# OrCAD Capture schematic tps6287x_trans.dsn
size D; title: TPS6287x: 2.7-V to 6-V Input Synchronous Buck Converter; rev: 1.0; note: Datasheet: <slvsfj3b>     EVM: <slvuc13>; note: Synchronous Step Down Converter
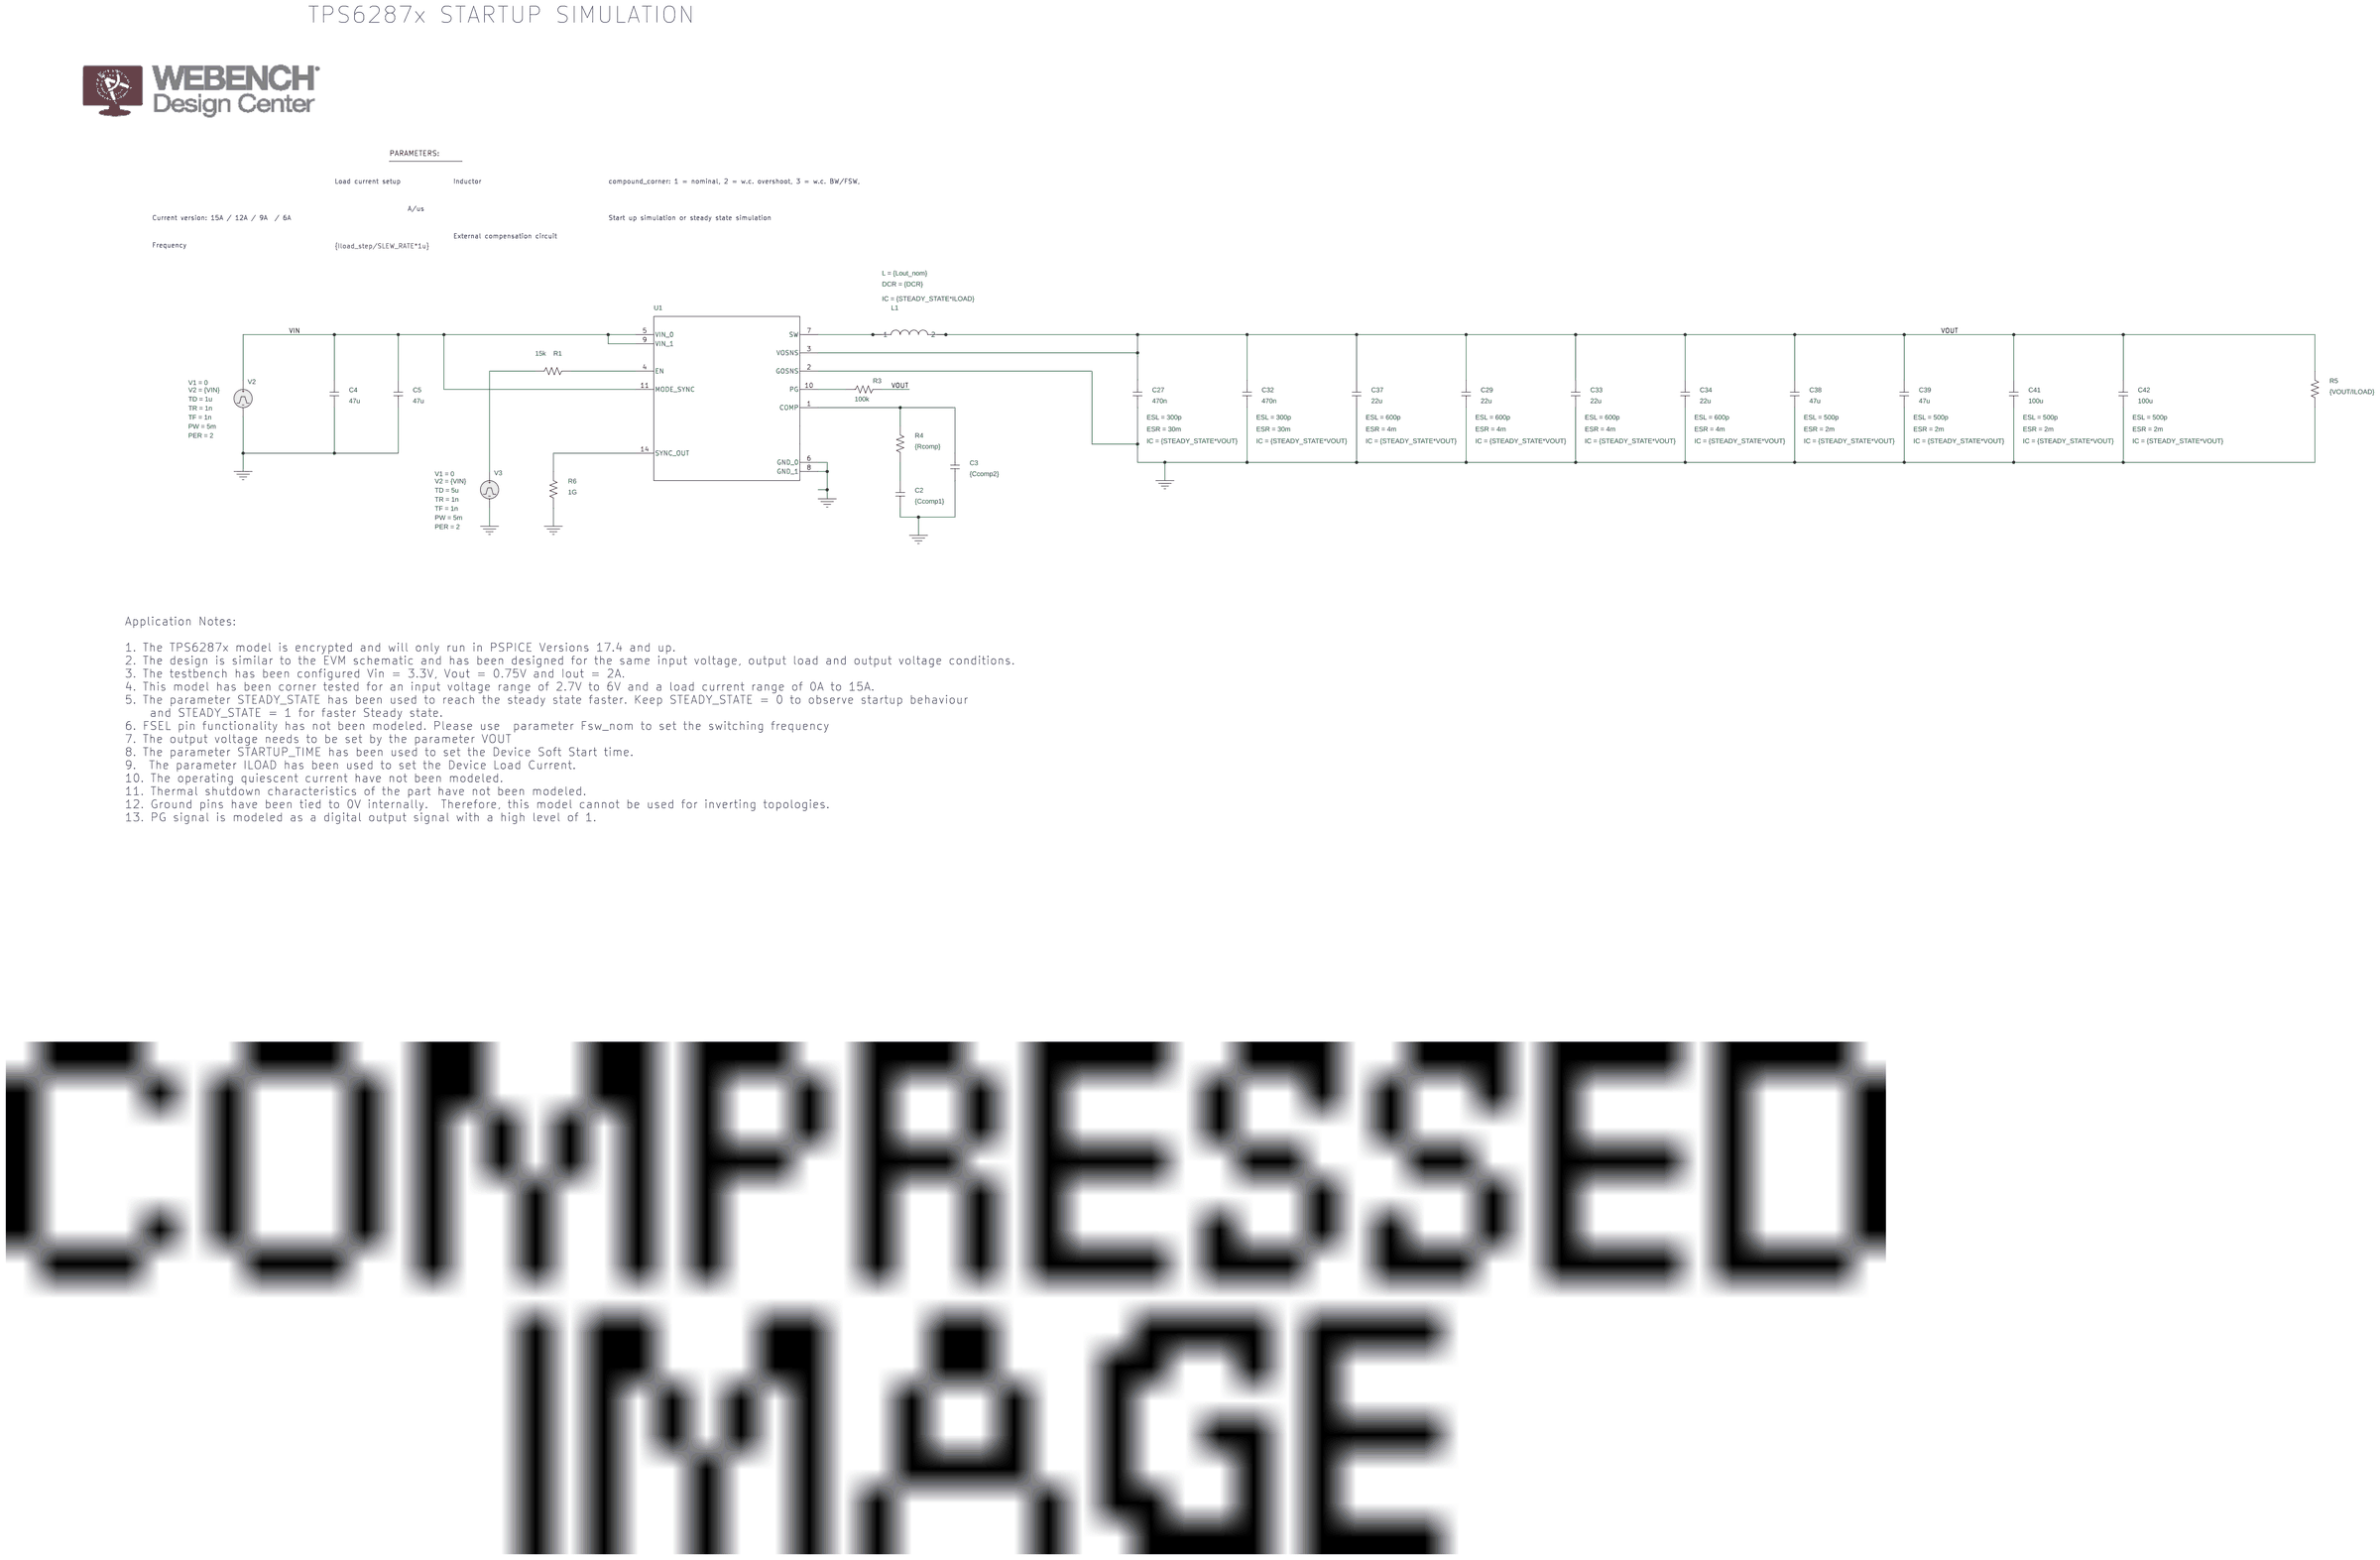
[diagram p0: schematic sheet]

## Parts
1  PARAM
C2  {Ccomp1}  [cap196]
C3  {Ccomp2}  [cap196]
C4  47u  [cap196]
C5  47u  [cap196]
C27  470n  [RAD/CK05]
C29  22u  [RAD/CK05]
C32  470n  [RAD/CK05]
C33  22u  [RAD/CK05]
C34  22u  [RAD/CK05]
C37  22u  [RAD/CK05]
C38  47u  [RAD/CK05]
C39  47u  [RAD/CK05]
C41  100u  [RAD/CK05]
C42  100u  [RAD/CK05]
L1  LDCR
R1  15k  [AXRC05]
R3  100k  [AXRC05]
R4  {Rcomp}  [AXRC05]
R5  {VOUT/ILOAD}  [AXRC05]
R6  1G  [AXRC05]
U1  Value  [RXS0016A-MFG]
V2  VPULSE
V3  VPULSE

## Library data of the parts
1 = PARAM: Ccomp1: 1.8n; Ccomp2: 10p; DCR: 1.7m; Fsw_nom: 3MEG; Fsw_tol_percent: 10; ILOAD: 2; IMAX: 15; Iload_pulse_delay: 60u; Iload_pulse_width: 30u; Iload_step: 10; Lout_nom: 110n; Lout_tol_percent: 20; Rcomp: 2.43k; SLEW_RATE: 20; STARTUP: {1-STEADY_STATE}; STARTUP_TIME: 0.3m; STEADY_STATE: 0; Trise: {Iload_step/SLEW_RATE*1u}; VIN: 3.3; VOUT: 0.75
C2-C5 = C
C27 C32 = C: AppProp: InductiveSlave:SRF;SRF:1.3403e+7;PrevCap:470n;PrevESL:300p; ESL: 300p; ESR: 30m; IC: {STEADY_STATE*VOUT}
C29 C33 C34 C37 = C: AppProp: InductiveSlave:SRF;SRF:1.3403e+7;PrevCap:470n;PrevESL:300p; ESL: 600p; ESR: 4m; IC: {STEADY_STATE*VOUT}
C38 C39 C41 C42 = C: AppProp: InductiveSlave:SRF;SRF:1.3403e+7;PrevCap:470n;PrevESL:300p; ESL: 500p; ESR: 2m; IC: {STEADY_STATE*VOUT}
L1 = LDCR: DCR: {DCR}; IC: {STEADY_STATE*ILOAD}; L: {Lout_nom}
R1 R3-R6 = R
U1 = TPS6287x_TRANS
V2 = VPULSE: PER: 2; PW: 5m; TD: 1u; TF: 1n; TR: 1n; V1: 0; V2: {VIN}
V3 = VPULSE: PER: 2; PW: 5m; TD: 5u; TF: 1n; TR: 1n; V1: 0; V2: {VIN}

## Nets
VIN: C4.2 C5.2 U1.5(VIN_0) U1.9(VIN_1) U1.11(MODE_SYNC) V2.1(+)
0: C2.1 C3.1 C4.1 C5.1 C27.2 C29.2 C32.2 C33.2 C34.2 C37.2 C38.2 C39.2 C41.2 C42.2 R5.1 R6.1 U1.2(GOSNS) U1.6(GND_0) U1.8(GND_1) V2.2(-) V3.2(-)
VOUT: C27.1 C29.1 C32.1 C33.1 C34.1 C37.1 C38.1 C39.1 C41.1 C42.1 L1.2 R3.2 R5.2 U1.3(VOSNS)
N16783952: L1.1 U1.7(SW)
N16784025: R1.2 V3.1(+)
N16784030: R1.1 U1.4(EN)
N16784102: R3.1 U1.10(PG)
N16784256: C3.2 R4.2 U1.1(COMP)
N16784313: R6.2 U1.14(SYNC_OUT)
N16784323: C2.2 R4.1

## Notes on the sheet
- TPS6287x STARTUP SIMULATION
- Load current setup
- Inductor
- compound_corner: 1 = nominal, 2 = w.c. overshoot, 3 = w.c. BW/FSW,
- A/us
- Current version: 15A / 12A / 9A  / 6A
- Start up simulation or steady state simulation
- External compensation circuit
- Frequency
- Application Notes:
  1. The TPS6287x model is encrypted and will only run in PSPICE Versions 17.4 and up.
  2. The design is similar to the EVM schematic and has been designed for the same input voltage, output load and output voltage conditions.
  3. The testbench has been configured Vin = 3.3V, Vout = 0.75V and Iout = 2A.
  4. This model has been corner tested for an input voltage range of 2.7V to 6V and a load current range of 0A to 15A.
  5. The parameter STEADY_STATE has been used to reach the steady state faster. Keep STEADY_STATE = 0 to observe startup behaviour
      and STEADY_STATE = 1 for faster Steady state.
  6. FSEL pin functionality has not been modeled. Please use  parameter Fsw_nom to set the switching frequency
  7. The output voltage needs to be set by the parameter VOUT
  8. The parameter STARTUP_TIME has been used to set the Device Soft Start time.
  9.  The parameter ILOAD has been used to set the Device Load Current.
  10. The operating quiescent current have not been modeled.
  11. Thermal shutdown characteristics of the part have not been modeled.
  12. Ground pins have been tied to 0V internally.  Therefore, this model cannot be used for inverting topologies.
  13. PG signal is modeled as a digital output signal with a high level of 1.
